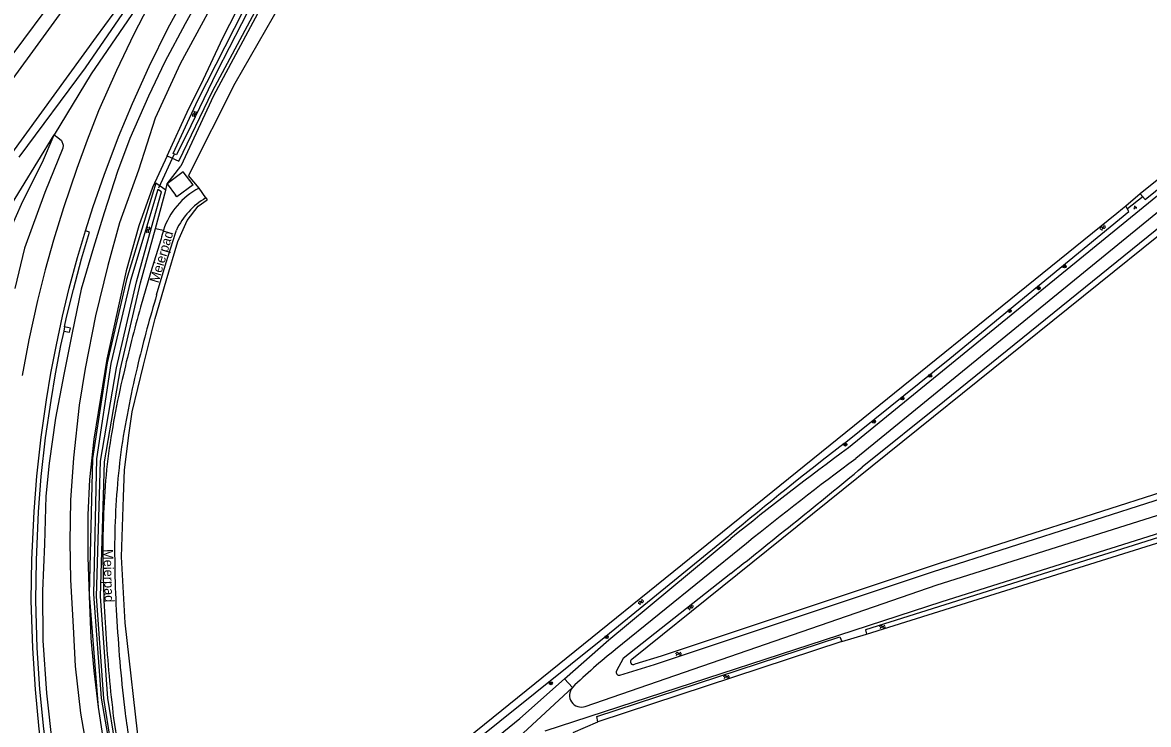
# Model space of a CAD drawing. Extents: x 135999 to 138000, y 396000 to 398501.
# Drawn here: x 137094.8 to 137389.8, y 396210.7 to 396394.6 of the extents above; entities that cross this region are included whole.
import ezdxf

# ---------------------------------------------------------------- set-up
doc = ezdxf.new("R2010")
doc.units = 0
for name, color, linetype in [('gg-afsc-draadraster', 7, 'Continuous'), ('gg-afsc-hekwerk', 7, 'Continuous'), ('gg-afsc-lijn draadraster', 7, 'Continuous'), ('gg-anno-openbare ruimte label', 7, 'Continuous'), ('gg-bbg-bijgebouw', 7, 'Continuous'), ('gg-knt-BGT kruinlijn', 7, 'Continuous'), ('gg-knt-bronhoudergrens', 7, 'Continuous'), ('gg-knt-onverhard', 7, 'Continuous'), ('gg-knt-verharding', 7, 'Continuous'), ('gg-kntw-bovenkant insteek waterloop', 7, 'Continuous'), ('gg-kntw-waterlijn', 7, 'Continuous'), ('gg-kwrk-duiker nz buis', 7, 'Continuous'), ('gt-grn-groengrens', 7, 'Continuous'), ('gt-grn-weggrens', 7, 'Continuous'), ('gt-symb-boom', 7, 'Continuous'), ('gt-symb-groenvak', 7, 'Continuous'), ('gt-symb-watersymbool', 7, 'Continuous'), ('gx-grn-maaiveld', 7, 'Continuous')]:
    doc.layers.add(name, color=color, linetype=linetype)

# ---------------------------------------------------------------- blocks, each defined once
blk = doc.blocks.new('gt0-WA')
at = {"layer": 'gt-symb-watersymbool'}
for centre, start, end in [((-0.32, 0.02), 28.0725, 151.9275), ((0.43, 0.42), 208.0725, 331.9275), ((-0.32, -0.43), 28.0725, 151.9275), ((0.43, -0.03), 208.0725, 331.9275)]:
    blk.add_arc(centre, 0.425, start, end, dxfattribs=at)
blk = doc.blocks.new('gt0-GRVAK')
at = {"layer": 'gt-symb-groenvak'}
for p, q in [((-0.11, 0.19), (-0.23, 0.24)), ((-0.18, 0.15), (0.09, 0.15)), ((-0.09, 0.21), (-0.16, 0.32)), ((-0.05, 0.21), (-0.05, 0.39)), ((0, 0.21), (0.06, 0.32)), ((0.02, 0.19), (0.13, 0.24)), ((0.26, -0.05), (0.2, 0.06)), ((0.3, -0.05), (0.3, 0.13)), ((0.35, -0.05), (0.41, 0.06)), ((-0.24, -0.23), (-0.36, -0.18)), ((-0.32, -0.26), (-0.05, -0.26)), ((-0.23, -0.21), (-0.29, -0.1)), ((-0.18, -0.2), (-0.18, -0.02)), ((-0.14, -0.21), (-0.07, -0.1)), ((-0.12, -0.23), (0, -0.18)), ((0.24, -0.07), (0.12, -0.02)), ((0.17, -0.11), (0.44, -0.11)), ((0.37, -0.07), (0.49, -0.02))]:
    blk.add_line(p, q, dxfattribs=at)
blk = doc.blocks.new('gt0-BOOM')
at = {"layer": 'gt-symb-boom'}
for radius in [0.4, 0.2]:
    blk.add_circle((0, 0), radius, dxfattribs=at)

msp = doc.modelspace()

# ---------------------------------------------------------------- linework, layer by layer
at = {"layer": 'gg-afsc-draadraster'}
for p, q in [((137132.62, 396352.33), (137136.26, 396356.99)), ((137132.35, 396350.73), (137132.62, 396352.33))]:
    msp.add_line(p, q, dxfattribs=at)
at = {"layer": 'gg-afsc-hekwerk'}
msp.add_lwpolyline([(137225.04, 396500), (137200.05, 396465.78), (137178.21, 396435.16), (137169.23, 396421.06), (137144.76, 396375.45), (137136.26, 396356.99)], dxfattribs=at)
msp.add_lwpolyline([(137225.04, 396500), (137200.05, 396465.78), (137178.21, 396435.16), (137169.23, 396421.06), (137144.76, 396375.45), (137136.26, 396356.99)], dxfattribs=at)
at = {"layer": 'gg-afsc-lijn draadraster'}
for p, q in [((137132.62, 396352.33), (137136.26, 396356.99)), ((137132.35, 396350.73), (137132.62, 396352.33))]:
    msp.add_line(p, q, dxfattribs=at)
at = {"layer": 'gg-bbg-bijgebouw'}
for p, q in [((137136.84, 396355.48), (137132.62, 396352.33)), ((137139.44, 396352.1), (137136.84, 396355.48)), ((137132.62, 396352.33), (137134.82, 396349.39))]:
    msp.add_line(p, q, dxfattribs=at)
msp.add_lwpolyline([(137139.44, 396352.1), (137135.19, 396348.92), (137134.82, 396349.39)], dxfattribs=at)
at = {"layer": 'gg-knt-BGT kruinlijn'}
for p, q in [((137111.27, 396382.76), (137126.68, 396405.28)), ((137142.9, 396404.28), (137137.4, 396394.27)), ((137137.4, 396394.27), (137132.08, 396384.3)), ((137132.08, 396384.3), (137127.75, 396375.29)), ((137093.86, 396359.32), (137111.27, 396382.76)), ((137127.75, 396375.29), (137122.92, 396364.26)), ((137103.02, 396365.17), (137104.06, 396364.46)), ((137104.06, 396364.46), (137104.95, 396363.73)), ((137104.95, 396363.73), (137105.44, 396362.5)), ((137122.92, 396364.26), (137119.66, 396355.6)), ((137105.3, 396361.68), (137100.6, 396350.05)), ((137105.44, 396362.5), (137105.3, 396361.68)), ((137119.66, 396355.6), (137116.14, 396344.73)), ((137100.6, 396350.05), (137095.32, 396335.47)), ((137116.14, 396344.73), (137113.39, 396335.65)), ((137095.32, 396335.47), (137092.76, 396324.96)), ((137113.39, 396335.65), (137110.14, 396324.77)), ((137110.14, 396324.77), (137107.79, 396313.34)), ((137107.79, 396313.34), (137105.58, 396302.36)), ((137105.58, 396302.36), (137103.37, 396290.96)), ((137103.37, 396290.96), (137101.79, 396279.16)), ((137101.79, 396279.16), (137100.87, 396270.51)), ((137100.87, 396270.51), (137100.55, 396257.96)), ((137100.55, 396257.96), (137100.04, 396245.7)), ((137100.04, 396245.7), (137100.07, 396232.7)), ((137100.07, 396232.7), (137101.02, 396218.89)), ((137101.02, 396218.89), (137102.64, 396204.64))]:
    msp.add_line(p, q, dxfattribs=at)
at = {"layer": 'gg-knt-bronhoudergrens'}
for p, q in [((137141.01, 396351.2), (137138.25, 396354.56)), ((137142.8, 396348.66), (137143.12, 396348.2))]:
    msp.add_line(p, q, dxfattribs=at)
for points in [[(137265.17, 396517.28), (137242.21, 396499.29), (137230.21, 396489.89), (137224.74, 396485.2), (137222.2, 396483.02), (137219.21, 396480.16), (137217.12, 396478.16), (137215.17, 396475.74), (137201.87, 396457.32), (137185.36, 396434.23), (137168.47, 396410.14), (137150.39, 396378.68), (137138.25, 396354.56)], [(137132.67, 396359.72), (137128.81, 396351.43), (137125.27, 396341.33), (137121.89, 396329.51), (137116.87, 396306.43), (137113.45, 396285.43), (137112.3, 396274.87), (137111.91, 396265.59), (137111.87, 396254.48), (137112.19, 396244.3), (137112.63, 396233.31), (137113.43, 396224.74), (137114.6, 396215.19)], [(137129.95, 396184.55), (137129, 396186.48), (137125.43, 396204.13), (137121.62, 396237.3), (137120.68, 396254.61), (137121.21, 396270.29), (137121.45, 396277.43), (137122.74, 396287.12), (137123.48, 396292.62), (137126.49, 396304.84), (137129.51, 396317.05), (137132.44, 396326.92), (137135.45, 396337.25), (137137.87, 396342.7), (137140.82, 396346.53), (137143.12, 396348.2)]]:
    msp.add_lwpolyline(points, dxfattribs=at)
at = {"layer": 'gg-knt-onverhard'}
for p, q in [((137446.97, 396394.03), (137311.17, 396283.2)), ((137449.92, 396392.01), (137313.08, 396280.33)), ((137284.46, 396258.12), (137250.14, 396230.33))]:
    msp.add_line(p, q, dxfattribs=at)
for points in [[(137242.22, 396215.39), (137334.36, 396247.25), (137415.18, 396272.78), (137449.62, 396283.47), (137473.58, 396292.1)], [(137231.73, 396208.99), (137335.7, 396242.93), (137445.61, 396277.57), (137475.02, 396287.88)], [(137236.75, 396222.59), (137248.35, 396232.89), (137280.36, 396259.44)], [(137164.66, 396162.8), (137166.94, 396164.99), (137225.07, 396212.21), (137236.75, 396222.59)]]:
    msp.add_lwpolyline(points, dxfattribs=at)
for centre, radius, start, end in [((137911.01, 395473.28), 1007.86, 126.52411, 128.73643), ((137838.35, 395573.97), 880.26, 126.636, 128.99383), ((137360.15, 396093.91), 175.25, 128.8831, 133.8141), ((137241.21, 396218.35), 3.13, 139.9104, 288.8147)]:
    msp.add_arc(centre, radius, start, end, dxfattribs=at)
at = {"layer": 'gg-knt-verharding'}
for p, q in [((137142.8, 396348.66), (137141.01, 396351.2)), ((137134.81, 396339.38), (137135.08, 396340.24))]:
    msp.add_line(p, q, dxfattribs=at)
for points in [[(137131.08, 396337.93), (137128.3, 396329.01), (137125.71, 396320.04)], [(137129.91, 396323.24), (137132.43, 396331.76), (137134.81, 396339.38)]]:
    msp.add_lwpolyline(points, dxfattribs=at)
for centre, radius, start, end in [((137149.81, 396334.27), 19.08, 117.4409, 161.9346), ((137152.42, 396332.07), 19.17, 120.1254, 154.7786), ((137149.71, 396334.29), 18.99, 161.9054, 168.95), ((137465.38, 396222.75), 350.2, 163.3257, 166.3402), ((137425.37, 396233.8), 311.82, 163.944, 167.2868), ((137369.66, 396245.62), 251.78, 166.2516, 171.356), ((137352.69, 396248.18), 237.77, 166.8124, 172.2329), ((137322, 396256.11), 203.11, 172.2615, 178.5986), ((137328.41, 396257.06), 212.59, 173.7207, 179.8896), ((137399.36, 396256.11), 280.46, 178.9853, 183.7516), ((137430.57, 396256.56), 314.75, 179.8344, 184.012), ((137503.28, 396259.27), 384.37, 183.2084, 186.8184), ((137492.11, 396257.72), 376.23, 183.5331, 186.9293), ((137352.22, 396246.4), 232.91, 188.0857, 191.6662), ((137321.88, 396240.79), 205.23, 187.9705, 191.6813)]:
    msp.add_arc(centre, radius, start, end, dxfattribs=at)
at = {"layer": 'gg-kntw-bovenkant insteek waterloop'}
for p, q in [((137481.1, 396425.51), (137387.58, 396349.7)), ((137254.39, 396227.76), (137428.43, 396367.9)), ((137132.67, 396359.72), (137135.74, 396358.3)), ((137132.35, 396350.73), (137129.65, 396352.57)), ((137129.57, 396340.67), (137132.35, 396350.73)), ((137381.5, 396344.62), (137209.44, 396205.47)), ((137315.91, 396234.3), (137440.62, 396273.53)), ((137309.43, 396232.41), (137245.53, 396211.37))]:
    msp.add_line(p, q, dxfattribs=at)
for points in [[(137135.74, 396358.3), (137144.52, 396376.65), (137167.49, 396419.63), (137176.44, 396434.09), (137199.55, 396466.35), (137224.17, 396500)], [(137387.58, 396349.7), (137388.86, 396348.28), (137446.24, 396394.53)], [(137453.09, 396389.83), (137336.35, 396295.42), (137314.75, 396278.07)], [(137129.65, 396352.57), (137122.01, 396327.27), (137116.9, 396305.44), (137113.06, 396280.37), (137112.26, 396244.81), (137114.6, 396215.19)], [(137310.04, 396284.31), (137337.74, 396306.57), (137384.59, 396345.13), (137383.86, 396346.53)], [(137383.86, 396346.53), (137382.92, 396345.77), (137381.5, 396344.62)], [(137118.97, 396206.17), (137117.09, 396217.59), (137115.24, 396244.2), (137116.21, 396279.54), (137120.4, 396303.88), (137125.64, 396326.4), (137129.57, 396340.67)], [(137251.28, 396223.62), (137260.32, 396226.35), (137333.17, 396250.64), (137413.9, 396276.5), (137448.18, 396287.29), (137484.84, 396299.66), (137526.4, 396312.91), (137552.5, 396321.51)], [(137476.38, 396298.41), (137449.93, 396289.49), (137415.65, 396278.7), (137334.92, 396252.83), (137262.07, 396228.55), (137255.17, 396226.46)], [(137440.62, 396273.53), (137440.33, 396274.78), (137315.59, 396235.44), (137315.91, 396234.3)], [(137209.44, 396205.47), (137210.52, 396204.11), (137247.6, 396233.84), (137279.86, 396260.09)], [(137280.34, 396250.24), (137252.17, 396227.93), (137250.4, 396224.7)], [(137245.53, 396211.37), (137245.21, 396212.77), (137308.92, 396233.67), (137309.43, 396232.41)]]:
    msp.add_lwpolyline(points, dxfattribs=at)
for centre, radius, start, end in [((137912.97, 395502.21), 987.53, 127.62862, 129.87412), ((135900.84, 397991.47), 2221.46, 308.38822, 309.52955), ((137254.78, 396227.11), 0.757, 120.9898, 300.7819), ((137251.06, 396224.34), 0.753, 151.1637, 286.7331)]:
    msp.add_arc(centre, radius, start, end, dxfattribs=at)
at = {"layer": 'gg-kntw-waterlijn'}
msp.add_line((137115.41, 396217.56), (137120.69, 396186.39), dxfattribs=at)
for points in [[(137272.62, 396566.58), (137263.24, 396554.64), (137243.62, 396527.98), (137212.09, 396485.15), (137193.54, 396460.39), (137176.83, 396437.11), (137170.37, 396427.03), (137160.75, 396410.82), (137155.38, 396400.67), (137145.67, 396381.68), (137138.82, 396367.59), (137135.08, 396359.92), (137134.21, 396360.34), (137140.68, 396374.3), (137152.65, 396397.76), (137160.56, 396412.48), (137165.31, 396420.39), (137177.18, 396438.92), (137190.74, 396457.83), (137210.64, 396484.8), (137228.78, 396509.84), (137245.44, 396532.46), (137264.17, 396557.38), (137272.38, 396567.73)], [(137128.56, 396340.95), (137131.14, 396350.29), (137130.24, 396350.9), (137123.03, 396327), (137117.93, 396305.24), (137114.11, 396280.28), (137113.32, 396244.84), (137115.41, 396217.56)], [(137117.93, 396205.99), (137116.04, 396217.47), (137114.19, 396244.18), (137115.17, 396279.64), (137119.37, 396304.09), (137124.62, 396326.66), (137128.56, 396340.95)]]:
    msp.add_lwpolyline(points, dxfattribs=at)
at = {"layer": 'gg-kwrk-duiker nz buis'}
for p, q in [((137134.49, 396360.14), (137130.39, 396351.24)), ((137384.27, 396345.89), (137388.38, 396349.1))]:
    msp.add_line(p, q, dxfattribs=at)
at = {"layer": 'gt-grn-groengrens'}
for p, q in [((137387.58, 396349.7), (137383.86, 396346.53)), ((137129.57, 396340.67), (137131.67, 396340.18)), ((137309.43, 396232.41), (137315.91, 396234.3)), ((137239.04, 396208.58), (137245.53, 396211.37))]:
    msp.add_line(p, q, dxfattribs=at)
at = {"layer": 'gt-grn-weggrens'}
for q in [(137236.75, 396222.59), (137219.14, 396202.15)]:
    msp.add_line((137238.82, 396220.37), q, dxfattribs=at)
at = {"layer": 'gx-grn-maaiveld'}
msp.add_line((137105.77, 396314.85), (137105.55, 396313.78), dxfattribs=at)
for points in [[(137133.65, 396441.23), (137105.67, 396404.63), (137078.96, 396368.72), (137048.15, 396325.96), (137019.81, 396285.64), (136993.48, 396247.19), (136974.95, 396219.28), (136972.37, 396215.34), (136969.92, 396210.72)], [(137136.48, 396439.46), (137115.83, 396412.43), (137088.61, 396375.11), (137066.87, 396344.85), (137042.62, 396310.62), (137017.83, 396274.76), (136994.06, 396239.67), (136972, 396207.11)], [(137111.23, 396340.02), (137113.28, 396346.42), (137116.14, 396354.65), (137119.91, 396364.71), (137123.55, 396373.44), (137127.91, 396383.07), (137132.91, 396393.21), (137138.42, 396403.28), (137142.93, 396411.1), (137148.69, 396420.21), (137153.85, 396428.21)], [(137143.56, 396425.93), (137139.82, 396420.14), (137132.98, 396408.62), (137128.84, 396401.07), (137123.93, 396391.58), (137119.39, 396382.06), (137114.69, 396371.46), (137111.73, 396363.76), (137109.02, 396356.4), (137105.52, 396346.09), (137102.84, 396337.58), (137100.69, 396329.84), (137098.71, 396321.75), (137096.4, 396311.46), (137094.66, 396302.09)], [(137143.56, 396425.93), (137143.44, 396426), (137112.73, 396381.15), (137103.02, 396365.17)], [(137158.27, 396427.08), (137154.15, 396419.74), (137149.22, 396408.13), (137136.1, 396383.82), (137129.51, 396369.58), (137125.18, 396355.94), (137120.2, 396342.11), (137117.16, 396330.93), (137113.89, 396317.8), (137111.18, 396303.92), (137109.58, 396294.31), (137108.15, 396280.56), (137107.34, 396269.46), (137107.16, 396258.52), (137107.32, 396248.54), (137108.04, 396236.28), (137108.58, 396225.93), (137109.98, 396213.6), (137113.95, 396190.54)], [(137132.67, 396359.72), (137138.36, 396372.06), (137141.61, 396378.45), (137147.24, 396390.58), (137152.73, 396401.42), (137159.15, 396412.6), (137164.18, 396420.57), (137165.5, 396422.83)], [(137122.8, 396402.88), (137114.04, 396390.91), (137091.84, 396360.28), (137064.83, 396322.66), (137037.4, 396283.33), (137013.92, 396248.92), (136989.01, 396211.59), (136978.75, 396195.51)], [(136985.46, 396182.66), (136988.25, 396186.5), (136994.55, 396193.45), (137001.29, 396201.92), (137042.9, 396265.43), (137073.49, 396314.29), (137090.21, 396344.26), (137103.02, 396365.17)], [(137090.8, 396338.74), (137094.86, 396347.82), (137100.03, 396358.02), (137103.02, 396365.17)], [(137111.31, 396154.77), (137110.25, 396154.49), (137107.47, 396164.77), (137105.2, 396173.78), (137102.56, 396186.82), (137100.77, 396196.9), (137099.17, 396209.42), (137098.14, 396219.86), (137097.45, 396230.69), (137097.07, 396243.14), (137097.21, 396253.78), (137097.8, 396266.45), (137098.48, 396275.73), (137099.62, 396285.93), (137101.09, 396295.75), (137102.21, 396302.76), (137103.67, 396310.19), (137105.24, 396317.64), (137107.02, 396324.98), (137109.15, 396333.02), (137111.23, 396340.02)], [(137105.77, 396314.85), (137106.31, 396317.4), (137108.09, 396324.7), (137110.21, 396332.72), (137112.29, 396339.71), (137111.23, 396340.02)], [(137105.55, 396313.78), (137104.75, 396309.97), (137103.29, 396302.56), (137102.17, 396295.58), (137100.71, 396285.79), (137099.58, 396275.62), (137098.9, 396266.38), (137098.31, 396253.74), (137098.17, 396243.15), (137098.55, 396230.74), (137099.23, 396219.95), (137100.26, 396209.55), (137101.86, 396197.07), (137103.64, 396187.03), (137106.28, 396174.02), (137108.53, 396165.05), (137111.31, 396154.77)], [(137105.55, 396313.78), (137107.08, 396313.45), (137107.32, 396314.53), (137105.77, 396314.85)], [(137114.6, 396215.19), (137117.06, 396199.26), (137119.97, 396184.98), (137120.76, 396181.14), (137121.45, 396178.4), (137122.73, 396175.64), (137124.1, 396173.25), (137126.14, 396170.61), (137128.81, 396167.98), (137132.03, 396165.27), (137149.26, 396152.48), (137150.32, 396151.96)]]:
    msp.add_lwpolyline(points, dxfattribs=at)

# ---------------------------------------------------------------- block references
at = {"layer": 'gt-symb-boom'}
for p in [(137367.76, 396330.73), (137360.98, 396325.01), (137353.39, 396319.05), (137332.57, 396302.05), (137325.3, 396296.13), (137317.82, 396290.04), (137310.35, 396284.04), (137247.81, 396233.6), (137233.18, 396221.48)]:
    msp.add_blockref('gt0-BOOM', p, dxfattribs=at)
at = {"layer": 'gt-symb-groenvak'}
msp.add_blockref('gt0-GRVAK', (137386.25, 396346.18), dxfattribs=at)
at = {"layer": 'gt-symb-watersymbool'}
for p, rotation in [((137139.77, 396370.6), 79.69002960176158), ((137127.68, 396340.34), -91.8919654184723), ((137377.78, 396340.82), 51.98433951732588), ((137256.78, 396242.71), 51.984339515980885), ((137269.79, 396241.32), 51.984339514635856), ((137320.04, 396236.25), 25.027278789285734), ((137266.58, 396229.19), 25.027278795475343), ((137279.15, 396223.17), 25.027278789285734)]:
    msp.add_blockref('gt0-WA', p, dxfattribs=dict(at, rotation=rotation))

# ---------------------------------------------------------------- texts
at = {"layer": 'gg-anno-openbare ruimte label'}
for rotation, p in [(73.6, (137130.39, 396326.2)), (271.4, (137115.97, 396256.6))]:
    msp.add_text('Meierpad', height=2.5, rotation=rotation, dxfattribs=at).set_placement(p)

doc.saveas('drawing.dxf')
